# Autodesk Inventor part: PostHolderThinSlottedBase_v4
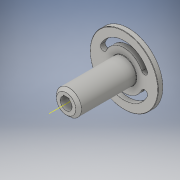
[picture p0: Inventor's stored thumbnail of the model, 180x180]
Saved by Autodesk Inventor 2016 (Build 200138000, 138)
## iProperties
Created: 2017-07
Part Number: PostHolderThinSlottedBase_v4
Material: Generic
Document SubType Name: Modeling
Designer: Name
Density: 1 g/cm^3
Appearance: Default
Author: Name
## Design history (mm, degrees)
sketch "Sketch1"
  geometry: C1 r 13.97 at (0, 0); 1 further point
  constraints: 1 centre point, 1 coincident
  dimensions: "d0" = 27.94 diameter of C1
extrude "Extrusion1" new body sketch "Sketch1" distance "d1" = 64.77; taper "d2" = 0 deg
sketch "Sketch2"
  geometry: C1 r 6.604 at (0, 0); 1 further point
  constraints: 1 centre point, 1 coincident
  dimensions: "d3" = 13.208 diameter of C1
extrude "Extrusion2" cut sketch "Sketch2" distance "d4" = 64.77; taper "d5" = 0 deg
sketch "Sketch3"
  geometry: L1 (3.175, 0)-(-3.175, 0); L2 (-3.175, 0)-(-3.175, 6.909); L3 (-3.175, 6.909)-(3.175, 6.909); L4 (3.175, 6.909)-(3.175, 0); 1 further point
  constraints: 8 end point, 2 parallel, 1 horizontal, 1 perpendicular
  dimensions: "d6" = 6.35 distance of L1.start L1.end; "d7" = 6.9088 distance of L1.end L2.end
extrude "Extrusion3" cut sketch "Sketch3" distance "d8" = 71.12; taper "d9" = 0 deg
workplane "Work Plane1"
sketch "Sketch4"
  geometry: 1 further point
sketch "Sketch5"
  geometry: L1 (13.97, 64.77)-(-13.97, 64.77) reference; L2 (-3.81, 64.77)-(3.81, 64.77); L3 (3.81, 64.77)-(3.81, 0); L4 (3.81, 0)-(-3.81, 0); L5 (-3.81, 0)-(-3.81, 64.77); L6 (3.175, 0)-(-3.175, 0) reference; 1 further point
  constraints: 8 end point, 2 parallel, 2 point on line, 1 collinear, 1 perpendicular
extrude "Extrusion4" cut sketch "Sketch5" distance "d11" = 1.905; taper "d12" = 0 deg
workaxis "Work Axis1"
chamfer "Chamfer1" distance "d13" = 3.175; stored, may be unused: second distance "d14" = 3.175, angle "d15" = 45 deg
sketch "Sketch6"
  geometry: C1 r 38.1 at (0, 0); 1 further point
  constraints: 1 centre point, 1 coincident
  dimensions: "d16" = 76.2 diameter of C1
extrude "Extrusion5" join sketch "Sketch6" distance "d17" = 5.334; taper "d18" = 0 deg
chamfer "Chamfer2" distance "d19" = 0.381; stored, may be unused: second distance "d20" = 3.175, angle "d21" = 45 deg
sketch "Sketch7"
  geometry: L1 (0, 0)-(23.02, 10.735); L2 (0, 0)-(-23.02, 10.735); L3 (0, 0)-(23.02, -10.735); L4 (0, 0)-(-23.02, -10.735); A1 r 25.4 centre (0, 0) between (23.02, 10.735) and (-23.02, 10.735); A2 r 28.854 centre (0, 0) between (26.151, 12.194) and (-26.151, 12.194); A3 r 21.946 centre (0, 0) between (19.889, 9.275) and (-19.889, 9.275); A4 r 3.454 centre (23.02, 10.735) between (19.889, 9.275) and (26.151, 12.194); A5 r 3.454 centre (-23.02, 10.735) between (-26.151, 12.194) and (-19.889, 9.275); A6 r 25.4 centre (0, 0) between (-23.02, -10.735) and (23.02, -10.735); A7 r 28.854 centre (0, 0) between (-26.151, -12.194) and (26.151, -12.194); A8 r 21.946 centre (0, 0) between (-19.889, -9.275) and (19.889, -9.275); A9 r 3.454 centre (-23.02, -10.735) between (-19.889, -9.275) and (-26.151, -12.194); A10 r 3.454 centre (23.02, -10.735) between (26.151, -12.194) and (19.889, -9.275); 1 further point
  constraints: 20 point on circle, 10 centre point, 8 end point, 8 tangent, 1 coincident
  dimensions: "d24" = 130 deg angle of L1 L2; "d25" = 6.9088 diameter of A5; "d27" = 130 deg angle of L4 L3; "d28" = 6.9088 diameter of A9; "d44" = 25.4 radius of A1
extrude "Extrusion6" cut sketch "Sketch7" stored distance "d29" = 5.334; taper "d30" = 0 deg
chamfer "Chamfer3" distance "d31" = 0.381; stored, may be unused: second distance "d32" = 3.175, angle "d33" = 45 deg
node "3D Sketch1"
sketch "Sketch8"
  geometry: C1 r 2.553 at (0, 33.516); C2 r 2.553 at (0, 53.848); C3 r 2.553 at (0, 13.208); 1 further point
  constraints: 3 centre point
  dimensions: "d34" = 5.1054 diameter of C1; "d35" = 5.1054 diameter of C2; "d36" = 5.1054 diameter of C3
extrude "Extrusion7" cut sketch "Sketch8" stored distance "d37" = 5.334; taper "d38" = 0 deg
sketch "Sketch9"
  geometry: C1 r 6.604 at (0, 0); 1 further point
  constraints: 1 centre point, 1 coincident
  dimensions: "d39" = 13.208 diameter of C1
extrude "Extrusion8" cut sketch "Sketch9" stored distance "d40" = 5.334; taper "d41" = 0 deg
sketch "Sketch10"
  geometry: L1 (-3.175, 6.909)-(3.175, 6.909) reference; L2 (-3.175, 6.909)-(3.175, 6.909); L3 (3.175, 6.909)-(3.175, 2.548); L4 (3.175, 2.548)-(-3.175, 2.548); L5 (-3.175, 2.548)-(-3.175, 6.909); 1 further point
  constraints: 8 end point, 2 parallel, 1 horizontal, 1 perpendicular
extrude "Extrusion9" cut sketch "Sketch10" stored distance "d42" = 5.334; taper "d43" = 0 deg
body "Solid1"
